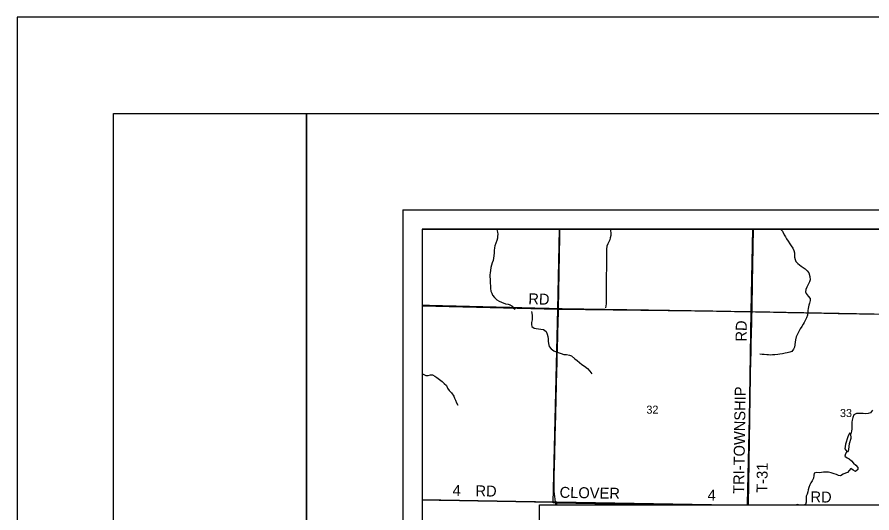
# Model space of a CAD drawing. Extents: x 0 to 34, y 0 to 22.
# Drawn here: x 0 to 4.43, y 19.428 to 22 of the extents above; entities that cross this region are included whole.
import ezdxf

# ---------------------------------------------------------------- set-up
doc = ezdxf.new("R2010")
doc.units = 0
for name, color, linetype in [('GM_X_Corporation', 7, 'Continuous'), ('GM_X_County_Road', 7, 'Continuous'), ('GM_X_County_Road_Text', 7, 'Continuous'), ('GM_X_Minor_Lake', 7, 'Continuous'), ('GM_X_Minor_River', 7, 'Continuous'), ('GM_X_Section_Text', 7, 'Continuous'), ('GM_X_State_Route', 7, 'Continuous'), ('GM_X_Township_Road', 7, 'Continuous'), ('GM_X_Township_Road_Text', 7, 'Continuous'), ('SH_Border', 7, 'Continuous'), ('SH_Cut_Line', 7, 'Continuous'), ('SH_Data', 7, 'Continuous'), ('SH_Text', 7, 'Continuous')]:
    doc.layers.add(name, color=color, linetype=linetype)

msp = doc.modelspace()

# ---------------------------------------------------------------- linework, layer by layer
at = {"layer": 'GM_X_Corporation'}
for points in [[(8.9, 20.9), (2.1, 20.9), (2.1, 14.1), (7.7244, 14.1)], [(7.8362, 20.9), (2.1, 20.9), (2.1, 19.4964), (2.7779, 19.4843), (2.7976, 19.484), (3.5996, 19.4692)], [(3.3876, 19.4692), (2.7977, 19.4799), (2.7791, 19.4803), (2.803, 20.4845), (3.8052, 20.472), (3.7881, 19.4692)], [(3.7881, 19.4692), (3.8052, 20.472), (4.8057, 20.4539), (4.7881, 19.4457), (4.7562, 19.4462)], [(3.5996, 19.4692), (2.7976, 19.484), (2.7779, 19.4843), (2.1, 19.4964), (2.1, 16.485), (2.253, 16.4822), (2.4333, 16.478), (2.4403, 16.4778), (2.5826, 16.473), (2.7595, 16.4724), (3.1897, 16.4617), (3.4295, 16.4557), (3.687, 16.4502), (3.6948, 16.4501), (3.7682, 16.4494), (4.2697, 16.4379), (4.8738, 16.4249)], [(2.7975, 19.4692), (2.7977, 19.4799), (3.3876, 19.4692)]]:
    msp.add_lwpolyline(points, dxfattribs=at)
for points in [[(2.8113, 20.9), (2.1, 20.9), (2.1, 20.5021), (2.803, 20.4845)], [(3.8131, 20.9), (2.8113, 20.9), (2.803, 20.4845), (3.8052, 20.472)], [(4.8158, 20.9), (3.8131, 20.9), (3.8052, 20.472), (4.8057, 20.4539)]]:
    msp.add_lwpolyline(points, close=True, dxfattribs=at)
at = {"layer": 'GM_X_County_Road'}
for points in [[(2.1, 20.5058), (2.1105, 20.5054), (2.1244, 20.5051), (2.1382, 20.5048), (2.1492, 20.5046), (2.1602, 20.5043), (2.1788, 20.5038), (2.1919, 20.5034), (2.2051, 20.5031), (2.2237, 20.5026), (2.2405, 20.5021), (2.2574, 20.5017), (2.276, 20.5013), (2.2946, 20.5008), (2.3103, 20.5004), (2.326, 20.5), (2.3446, 20.4996), (2.3633, 20.4992), (2.3795, 20.4988), (2.3956, 20.4984), (2.4137, 20.498), (2.4317, 20.4976), (2.4503, 20.4971), (2.4689, 20.4966), (2.4829, 20.4962), (2.497, 20.4959), (2.5156, 20.4954), (2.5342, 20.4949), (2.5529, 20.4944), (2.566, 20.494), (2.5791, 20.4936), (2.5978, 20.4932), (2.6164, 20.4927), (2.6316, 20.4923), (2.6467, 20.4919), (2.6654, 20.4915), (2.684, 20.4911), (2.7026, 20.4907), (2.7212, 20.4903), (2.7398, 20.4898), (2.7576, 20.4894), (2.7753, 20.4889), (2.7874, 20.4886), (2.7995, 20.4883), (2.806, 20.4877), (2.8246, 20.4874), (2.8433, 20.4871), (2.8619, 20.4868), (2.8805, 20.4866), (2.8992, 20.4863), (2.9178, 20.486), (2.9365, 20.4857), (2.9551, 20.4854), (2.9738, 20.4852), (2.9924, 20.4849), (3.011, 20.4846), (3.0297, 20.4843), (3.0483, 20.484), (3.067, 20.4838), (3.0856, 20.4835), (3.1042, 20.4832), (3.1229, 20.4829), (3.1415, 20.4827), (3.1602, 20.4824), (3.1788, 20.4821), (3.1974, 20.4818), (3.2161, 20.4815), (3.2347, 20.4812), (3.2534, 20.481), (3.272, 20.4807), (3.2897, 20.4804), (3.3074, 20.4801), (3.326, 20.4798), (3.3447, 20.4795), (3.3633, 20.4792), (3.3819, 20.4789), (3.4006, 20.4786), (3.4192, 20.4783), (3.4379, 20.478), (3.4565, 20.4777), (3.4751, 20.4774), (3.4938, 20.4771), (3.5124, 20.4768), (3.5311, 20.4765), (3.5497, 20.4762), (3.5683, 20.4759), (3.587, 20.4756), (3.6056, 20.4753), (3.6243, 20.475), (3.6429, 20.4747), (3.6615, 20.4744), (3.6802, 20.4741), (3.6988, 20.4738), (3.7175, 20.4735), (3.7361, 20.4732), (3.7548, 20.4729), (3.7734, 20.4726), (3.7911, 20.4723), (3.8088, 20.4721), (3.8275, 20.4717), (3.8461, 20.4713), (3.8647, 20.4709), (3.8834, 20.4706), (3.902, 20.4702), (3.9206, 20.4698), (3.9393, 20.4694), (3.9579, 20.4691), (3.9765, 20.4687), (3.9952, 20.4683), (4.0138, 20.4679), (4.0324, 20.4676), (4.0511, 20.4672), (4.0697, 20.4668), (4.0883, 20.4664), (4.107, 20.4661), (4.1256, 20.4657), (4.1442, 20.4653), (4.1629, 20.4649), (4.1815, 20.4646), (4.2002, 20.4642), (4.2188, 20.4638), (4.2374, 20.4634), (4.2561, 20.4631), (4.2747, 20.4627), (4.2923, 20.4623), (4.31, 20.462), (4.3286, 20.4617), (4.3473, 20.4615), (4.3659, 20.4613), (4.3845, 20.4611), (4.4032, 20.4608), (4.4218, 20.4606), (4.4405, 20.4604)], [(2.1, 19.4962), (2.1121, 19.496), (2.1307, 19.4957), (2.1494, 19.4954), (2.168, 19.4951), (2.1866, 19.4947), (2.2053, 19.4944), (2.2239, 19.4941), (2.2426, 19.4938), (2.2612, 19.4935), (2.2781, 19.4932), (2.295, 19.4929), (2.3136, 19.4926), (2.3323, 19.4923), (2.3509, 19.492), (2.3695, 19.4916), (2.3882, 19.4913), (2.4068, 19.491), (2.4255, 19.4907), (2.4441, 19.4904), (2.4627, 19.49), (2.4814, 19.4897), (2.5, 19.4894), (2.5187, 19.4891), (2.5373, 19.4888), (2.556, 19.4884), (2.5746, 19.4881), (2.5932, 19.4878), (2.6119, 19.4875), (2.6305, 19.4872), (2.6492, 19.4868), (2.6678, 19.4865), (2.6864, 19.4862), (2.7051, 19.4859), (2.7237, 19.4856), (2.7424, 19.4852), (2.761, 19.4849), (2.7755, 19.4847), (2.7901, 19.4844), (2.8087, 19.4841), (2.8274, 19.4837), (2.846, 19.4834), (2.8646, 19.483), (2.8833, 19.4827), (2.9019, 19.4823), (2.9205, 19.4819), (2.9392, 19.4816), (2.9578, 19.4812), (2.9764, 19.4809), (2.9951, 19.4805), (3.0137, 19.4802), (3.0323, 19.4798), (3.051, 19.4795), (3.0696, 19.4791), (3.0882, 19.4788), (3.1069, 19.4784), (3.1255, 19.4781), (3.1442, 19.4777), (3.1628, 19.4774), (3.1814, 19.477), (3.2001, 19.4767), (3.2187, 19.4763), (3.2373, 19.476), (3.256, 19.4756), (3.2701, 19.4754), (3.2842, 19.4751), (3.3029, 19.4747), (3.3215, 19.4744), (3.3401, 19.474), (3.3588, 19.4737), (3.3774, 19.4733), (3.396, 19.4729), (3.4147, 19.4726), (3.4333, 19.4722), (3.452, 19.4718), (3.4706, 19.4715), (3.4892, 19.4711), (3.5079, 19.4708), (3.5265, 19.4704), (3.5451, 19.47), (3.5638, 19.4697), (3.5824, 19.4693), (3.5877, 19.4692)]]:
    msp.add_lwpolyline(points, dxfattribs=at)
at = {"layer": 'GM_X_Minor_Lake'}
for points in [[(4.3215, 19.8386), (4.3136, 19.8408), (4.3051, 19.8225), (4.2942, 19.7849), (4.2906, 19.7594), (4.3005, 19.7464), (4.3064, 19.746)], [(4.3064, 19.746), (4.3112, 19.757), (4.3136, 19.7873), (4.3233, 19.8153), (4.3215, 19.8386)]]:
    msp.add_lwpolyline(points, dxfattribs=at)
at = {"layer": 'GM_X_Minor_River'}
for points in [[(2.4855, 20.9), (2.4871, 20.8972), (2.4899, 20.8835), (2.4908, 20.8739), (2.4901, 20.8626), (2.4895, 20.8527), (2.4866, 20.8402), (2.481, 20.8278), (2.4754, 20.8139), (2.4736, 20.8037), (2.4729, 20.7897), (2.4726, 20.7767), (2.4708, 20.7612), (2.469, 20.7487), (2.4676, 20.7377), (2.4627, 20.7246), (2.4587, 20.7136), (2.4554, 20.7012), (2.4528, 20.686), (2.4513, 20.6732), (2.4503, 20.6633), (2.4509, 20.6527), (2.451, 20.6401), (2.4515, 20.6291), (2.4524, 20.6185), (2.4532, 20.607), (2.454, 20.5918), (2.456, 20.5789), (2.4599, 20.567), (2.4642, 20.5567), (2.4735, 20.5451), (2.4868, 20.533), (2.4985, 20.5263), (2.5097, 20.5203), (2.5308, 20.513), (2.5444, 20.5108), (2.5546, 20.5079), (2.5658, 20.4997), (2.572, 20.4897), (2.5807, 20.484)], [(3.0742, 20.9), (3.0761, 20.8927), (3.077, 20.8798), (3.0767, 20.8661), (3.0741, 20.854), (3.0716, 20.8442), (3.0665, 20.8344), (3.0613, 20.8239), (3.0569, 20.8122), (3.0554, 20.7967), (3.0554, 20.7796), (3.0551, 20.7701), (3.0551, 20.7534), (3.0549, 20.7424), (3.0551, 20.7329), (3.0552, 20.723), (3.0552, 20.7071), (3.0554, 20.6957), (3.0548, 20.6858), (3.0537, 20.6722), (3.0527, 20.63), (3.0533, 20.6201), (3.053, 20.6087), (3.0531, 20.5954), (3.0536, 20.5833), (3.0537, 20.57), (3.0534, 20.5601), (3.0537, 20.5366), (3.0534, 20.5263), (3.0523, 20.5123), (3.0514, 20.502), (3.0496, 20.4918)], [(3.9562, 20.9), (3.9664, 20.8894), (3.9762, 20.8705), (3.982, 20.8598), (3.9871, 20.8502), (3.9959, 20.8367), (4.0047, 20.8235), (4.012, 20.8127), (4.0201, 20.8019), (4.0259, 20.7889), (4.0291, 20.777), (4.0284, 20.7653), (4.0285, 20.7542)], [(4.0285, 20.7542), (4.0317, 20.7416), (4.0356, 20.7317), (4.0471, 20.7211), (4.0632, 20.7086), (4.0748, 20.7015), (4.0848, 20.6937), (4.0952, 20.6836), (4.1026, 20.6724), (4.1086, 20.6548), (4.1101, 20.6373), (4.1065, 20.6271), (4.0929, 20.5993), (4.0873, 20.5865), (4.0863, 20.5755), (4.0899, 20.5656), (4.1006, 20.552), (4.1094, 20.5404), (4.1103, 20.5302), (4.1066, 20.5162), (4.1029, 20.5053), (4.0991, 20.4879), (4.0982, 20.478), (4.0979, 20.4674), (4.0965, 20.4545), (4.0912, 20.4395), (4.0841, 20.4267), (4.0785, 20.4158), (4.0734, 20.4061), (4.0663, 20.3948), (4.0588, 20.3821), (4.0509, 20.3682), (4.0449, 20.3558), (4.0385, 20.3404), (4.0336, 20.3257), (4.0318, 20.3128), (4.029, 20.2871), (4.0242, 20.2773), (4.0156, 20.2646), (4.0049, 20.261), (3.9907, 20.258), (3.9808, 20.2559), (3.9675, 20.2536), (3.9523, 20.2512), (3.942, 20.2496), (3.9268, 20.2477), (3.9143, 20.2472), (3.9048, 20.247), (3.8949, 20.2473), (3.8851, 20.2482), (3.8722, 20.2497), (3.862, 20.2503), (3.8502, 20.2506)], [(2.6664, 20.4731), (2.6677, 20.4636), (2.669, 20.4518), (2.6703, 20.4419), (2.6692, 20.4294), (2.6667, 20.4161), (2.6668, 20.4055), (2.6681, 20.3952), (2.6793, 20.387), (2.6902, 20.3841), (2.7016, 20.3831), (2.7144, 20.3813), (2.728, 20.3787), (2.7426, 20.3696), (2.748, 20.3558), (2.75, 20.3432), (2.752, 20.3314), (2.7532, 20.3185), (2.7541, 20.3059), (2.7572, 20.2918), (2.7679, 20.2783), (2.7821, 20.2685), (2.7933, 20.2636), (2.8193, 20.2543), (2.8336, 20.2502), (2.848, 20.2503), (2.8624, 20.2469), (2.8736, 20.2425), (2.8908, 20.2273), (2.9031, 20.2186), (2.9139, 20.2089), (2.9273, 20.198), (2.94, 20.1889), (2.956, 20.1764), (2.9682, 20.1632), (2.9793, 20.1497)], [(2.1, 20.1519), (2.1041, 20.1482), (2.118, 20.1407), (2.1301, 20.14), (2.1423, 20.1439), (2.1529, 20.1437), (2.1642, 20.1377), (2.1758, 20.1295), (2.1888, 20.1197), (2.2023, 20.1099), (2.2134, 20.099), (2.2253, 20.0881), (2.2303, 20.0747), (2.2387, 20.0623), (2.2521, 20.0503), (2.2627, 20.0329), (2.2671, 20.0229), (2.2714, 20.0126), (2.2775, 19.9992), (2.2837, 19.9869)], [(4.4115, 19.9432), (4.3982, 19.9424), (4.3846, 19.9435), (4.3607, 19.944), (4.3505, 19.9439), (4.337, 19.9366), (4.3314, 19.9227), (4.3277, 19.9095), (4.3267, 19.8981), (4.3264, 19.8879), (4.3265, 19.8765), (4.3266, 19.8639), (4.3245, 19.8511), (4.3215, 19.8386)], [(4.4339, 19.9609), (4.423, 19.9475), (4.4115, 19.9432)], [(4.3005, 19.7464), (4.2938, 19.7348), (4.2893, 19.7227), (4.302, 19.7129), (4.3117, 19.7078), (4.3236, 19.6972), (4.3347, 19.6852), (4.347, 19.6754), (4.357, 19.663), (4.3571, 19.6524), (4.3444, 19.6432), (4.3328, 19.6496), (4.3208, 19.6582), (4.3115, 19.647), (4.3037, 19.6369), (4.2938, 19.6345), (4.2811, 19.6291), (4.268, 19.6207), (4.2574, 19.6224), (4.2462, 19.6265), (4.2349, 19.6309), (4.2198, 19.6358), (4.2055, 19.6384), (4.1907, 19.6395), (4.1789, 19.6394), (4.1686, 19.637), (4.1572, 19.6365), (4.1436, 19.6376), (4.131, 19.6345), (4.1285, 19.6212), (4.127, 19.6087), (4.121, 19.5944), (4.1143, 19.5847), (4.1077, 19.5738), (4.1039, 19.5595), (4.1006, 19.5467), (4.0985, 19.5365), (4.0948, 19.5251), (4.0896, 19.515), (4.089, 19.5048), (4.0899, 19.4949), (4.0901, 19.4835), (4.086, 19.4714), (4.0757, 19.4675), (4.0658, 19.4673), (4.056, 19.4683), (4.0454, 19.4708), (4.0395, 19.4692)]]:
    msp.add_lwpolyline(points, dxfattribs=at)
at = {"layer": 'GM_X_State_Route'}
for points in [[(2.7901, 19.4844), (2.7885, 19.4987), (2.7868, 19.5129), (2.7856, 19.5262), (2.7843, 19.5395), (2.7837, 19.5497), (2.7832, 19.5599), (2.783, 19.5707), (2.7828, 19.5815), (2.7833, 19.6001), (2.7838, 19.6187), (2.7842, 19.6374), (2.7847, 19.656), (2.7852, 19.6747), (2.7856, 19.6933), (2.7861, 19.7119), (2.7866, 19.7306), (2.787, 19.7492), (2.7875, 19.7678), (2.788, 19.7865), (2.7885, 19.8051), (2.7889, 19.8237), (2.7894, 19.8424), (2.7899, 19.861), (2.7903, 19.8796), (2.7908, 19.8983), (2.7913, 19.9169), (2.7917, 19.9355), (2.7922, 19.9542), (2.7926, 19.9709), (2.793, 19.9876), (2.7935, 20.0063), (2.794, 20.0249), (2.7945, 20.0435), (2.795, 20.0622), (2.7955, 20.0808), (2.7959, 20.0994), (2.7964, 20.1181), (2.7969, 20.1367), (2.7974, 20.1553), (2.7979, 20.174), (2.7984, 20.1926), (2.7988, 20.2112), (2.7993, 20.2299), (2.7998, 20.2485), (2.8003, 20.2671), (2.8008, 20.2858), (2.8012, 20.3044), (2.8017, 20.323), (2.8022, 20.3417), (2.8027, 20.3603), (2.8032, 20.379), (2.8037, 20.3976), (2.8041, 20.4162), (2.8046, 20.4349), (2.8051, 20.4535), (2.8055, 20.4706), (2.806, 20.4877), (2.8063, 20.5063), (2.8067, 20.525), (2.807, 20.5436), (2.8074, 20.5622), (2.8077, 20.5809), (2.808, 20.5995), (2.8084, 20.6181), (2.8087, 20.6368), (2.8091, 20.6554), (2.8094, 20.674), (2.8098, 20.6927), (2.8101, 20.7113), (2.8105, 20.7299), (2.8108, 20.7486), (2.8111, 20.7672), (2.8115, 20.7858), (2.8118, 20.8045), (2.8122, 20.8231), (2.8125, 20.8417), (2.8129, 20.8604), (2.8132, 20.879), (2.8136, 20.8977), (2.8136, 20.9)], [(2.7919, 19.4692), (2.7915, 19.4728), (2.7901, 19.4844)]]:
    msp.add_lwpolyline(points, dxfattribs=at)
at = {"layer": 'GM_X_Township_Road'}
msp.add_lwpolyline([(3.7853, 19.4692), (3.7857, 19.484), (3.7861, 19.5026), (3.7866, 19.5212), (3.787, 19.5399), (3.7874, 19.5585), (3.7879, 19.5772), (3.7883, 19.5958), (3.7887, 19.6144), (3.7892, 19.6331), (3.7896, 19.6517), (3.79, 19.6703), (3.7904, 19.689), (3.7909, 19.7076), (3.7913, 19.7262), (3.7917, 19.7449), (3.7922, 19.7635), (3.7926, 19.7821), (3.793, 19.8008), (3.7935, 19.8194), (3.7939, 19.838), (3.7943, 19.8567), (3.7948, 19.8753), (3.7952, 19.8939), (3.7956, 19.9126), (3.7961, 19.9312), (3.7965, 19.9499), (3.7967, 19.9595), (3.7969, 19.9691), (3.7974, 19.9877), (3.7978, 20.0063), (3.7983, 20.025), (3.7987, 20.0436), (3.7991, 20.0623), (3.7996, 20.0809), (3.8, 20.0995), (3.8005, 20.1182), (3.8009, 20.1368), (3.8014, 20.1554), (3.8018, 20.1741), (3.8022, 20.1927), (3.8027, 20.2113), (3.8031, 20.23), (3.8036, 20.2486), (3.804, 20.2672), (3.8044, 20.2859), (3.8049, 20.3045), (3.8053, 20.3231), (3.8058, 20.3418), (3.8062, 20.3604), (3.8066, 20.379), (3.8071, 20.3977), (3.8075, 20.4163), (3.8079, 20.4349), (3.8084, 20.4535), (3.8088, 20.4721), (3.8092, 20.4907), (3.8095, 20.5093), (3.8098, 20.528), (3.8102, 20.5466), (3.8105, 20.5653), (3.8108, 20.5839), (3.8112, 20.6025), (3.8115, 20.6212), (3.8118, 20.6398), (3.8122, 20.6585), (3.8125, 20.6771), (3.8128, 20.6957), (3.8135, 20.733), (3.8139, 20.7517), (3.8142, 20.7703), (3.8145, 20.7889), (3.8149, 20.8076), (3.8152, 20.8262), (3.8155, 20.8449), (3.8159, 20.8635), (3.8162, 20.8822), (3.8165, 20.9)], dxfattribs=at)
at = {"layer": 'SH_Border'}
for points in [[(0.5, 21.5), (1.5, 21.5), (1.5, 0.5), (0.5, 0.5)], [(1.5, 21.5), (33.5, 21.5), (33.5, 0.5), (1.5, 0.5)]]:
    msp.add_lwpolyline(points, close=True, dxfattribs=at)
at = {"layer": 'SH_Cut_Line'}
msp.add_lwpolyline([(0, 0), (34, 0), (34, 22), (0, 22)], close=True, dxfattribs=at)
at = {"layer": 'SH_Data'}
for p, q in [((2, 21), (9, 21)), ((2, 21), (2, 14)), ((2.1, 20.9), (2.1, 14.1)), ((2.1, 20.9), (8.9, 20.9)), ((2.1, 20.9), (2.1, 14.1)), ((2.1, 20.9), (8.9, 20.9))]:
    msp.add_line(p, q, dxfattribs=at)
at = {"layer": 'SH_Text'}
msp.add_lwpolyline([(2.7075, 19.4692), (4.7562, 19.4692), (4.7562, 18.8986), (2.7075, 18.8986)], close=True, dxfattribs=at)

# ---------------------------------------------------------------- texts
at = {"layer": 'GM_X_County_Road_Text'}
for s, height, rotation, p in [('RD', 0.05682, 358.5184, (2.649, 20.5106)), ('4', 0.0568, 358.8968, (2.2564, 19.5164)), ('RD', 0.05682, 358.5184, (2.3749, 19.5148)), ('CLOVER', 0.05682, 358.9677, (2.8114, 19.5064)), ('4', 0.0568, 358.8989, (3.5781, 19.4923)), ('RD', 0.05682, 359.0128, (4.1113, 19.4831))]:
    msp.add_text(s, height=height, rotation=rotation, dxfattribs=at).set_placement(p)
at = {"layer": 'GM_X_Section_Text'}
for s, p in [('32', (3.2614, 19.9425)), ('33', (4.2647, 19.925))]:
    msp.add_text(s, height=0.04186, rotation=0, dxfattribs=at).set_placement(p)
at = {"layer": 'GM_X_Township_Road_Text'}
for s, height, rotation, p in [('RD', 0.05682, 89.0128, (3.7803, 20.3161)), ('TRI-TOWNSHIP', 0.056818, 89.1306, (3.7678, 19.5261)), ('T-31', 0.05682, 89.2931, (3.8887, 19.532))]:
    msp.add_text(s, height=height, rotation=rotation, dxfattribs=at).set_placement(p)

doc.saveas('drawing.dxf')
